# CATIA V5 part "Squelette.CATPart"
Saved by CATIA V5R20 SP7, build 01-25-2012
Part number: Squelette
Publications: "Plan_sym", "Plan_bout", "Plan_bielle1", "Plan_bielle2/3", "Plan_verin", "Point_bielle_21", "Point_bielle_22", "Point_bielle_31", "Point_bielle_32", "Point_bielle_11", "Point_bielle_12", "X21", "Y21", "X22", "Y22", "X31", "Y31", "X32", "Y32", "Point_courbeguide", "Courbe_guide", "Point_centre_tige_verin", "Xptv", "Yptv"
Bounding box of the stored display mesh (mm): x 0 to 250, y -9 to 104, z 41 to 118
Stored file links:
  F:\Travaux\Modélisations\CFAO_2011\MMS\MMS_GR2\AA_OK\tquattrone\Catia\Squelette.CATPart
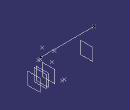
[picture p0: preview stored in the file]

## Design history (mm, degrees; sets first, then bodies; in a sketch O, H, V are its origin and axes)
Parameters
  X21 = 104 mm
  Y21 = 41 mm
  X22 = 44 mm
  Y22 = 83 mm
  X31 = -9 mm
  Y31 = 67 mm
  X32 = 0 mm
  Y32 = 118 mm
  Xpcg = 33.627 mm
  Ypcg = 116.727 mm
  Xptv = 27.5 mm
  Yptv = 102.496 mm
Set1 "Set_geometrique1"
  Plane1 "Plan_sym": type Offset, RefPlane yz-plane, Offset 0
  Plane2 "Plan_bout": type Offset, RefPlane yz-plane, Offset 250
  Plane3 "Plan_bielle1": type Offset, RefPlane yz-plane, Offset 220
  Plane4 "Plan_bielle2/3": type Offset, RefPlane yz-plane, Offset 210
  Plane5 "Plan_verin": type Offset, RefPlane yz-plane, Offset 180
  Point1 "Point_bielle_21": type OnPlane, Support Plane4, H 104 {= X21}, V 41 {= Y21}, Direction (0, 1, 0)
  Point2 "Point_bielle_22": type OnPlane, Support Plane4, H 44 {= X22}, V 83 {= Y22}, Direction (0, 1, 0)
  Point3 "Point_bielle_31": type OnPlane, Support Plane4, H -9 {= X31}, V 67 {= Y31}, Direction (0, 1, 0)
  Point4 "Point_bielle_32": type OnPlane, Support Plane4, H 0 {= X32}, V 118 {= Y32}, Direction (0, 1, 0)
  Point5 "Point_bielle_11": type OnPlane, Support Plane3, H 104 {= X21}, V 41 {= Y21}, Direction (0, 1, 0)
  Point6 "Point_bielle_12": type OnPlane, Support Plane3, H -9 {= X31}, V 67 {= Y31}, Direction (0, 1, 0)
  Point7 "Point_courbeguide": type OnPlane, Support Plane1, H 33.627 {= Xpcg}, V 116.727 {= Ypcg}, Direction (0, 1, 0)
  Line1 "Courbe_guide": type Normal, LineFirstUpto Plane2, LineSecondUpto Plane1, RefPoint Point7, Start 0, End 20
  Point8 "Point_centre_tige_verin": type OnPlane, Support Plane5, H 27.5 {= Xptv}, V 102.496 {= Yptv}, Direction (0, 1, 0)
Body1 (main body)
